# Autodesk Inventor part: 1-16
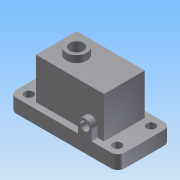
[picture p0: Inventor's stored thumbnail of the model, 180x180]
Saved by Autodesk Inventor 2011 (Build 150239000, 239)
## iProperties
Created: 2014-02
Part Number: 1-16
Document SubType Name: Modeling
Designer: Administrator
Density: 1 g/cm^3
Author: Administrator
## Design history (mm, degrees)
sketch "草图1"
  geometry: L1 (-15.86, 7.751)-(15.86, 7.751); L2 (15.86, 7.751)-(15.86, -7.751); L3 (15.86, -7.751)-(-15.86, -7.751); L4 (-15.86, -7.751)-(-15.86, 7.751); 3 further points
  constraints: 8 end point, 2 midpoint, 2 parallel, 1 horizontal, 1 horizontal alignment, 1 perpendicular, 1 vertical alignment
extrude "拉伸1" new body sketch "草图1" distance "d0" = 4; taper "d1" = 0 deg
sketch "草图2"
  geometry: L1 (-9.931, 5.952)-(9.994, 5.952); L2 (9.994, 5.952)-(9.994, -5.952); L3 (9.994, -5.952)-(-9.931, -5.952); L4 (-9.931, -5.952)-(-9.931, 5.952); 1 further point
  constraints: 8 end point, 2 parallel, 1 horizontal, 1 perpendicular
extrude "拉伸2" join sketch "草图2" distance "d2" = 12; taper "d3" = 0 deg
sketch "草图3"
  geometry: L1 (-9.994, -5.952)-(9.931, -5.952) reference; L2 (-9.994, 5.952)-(-9.994, -5.952) reference; L3 (9.931, 5.952)-(-9.994, 5.952) reference; L4 (9.931, -5.952)-(9.931, 5.952) reference; L5 (-7.989, -4.012)-(7.989, -4.012); L6 (7.989, -4.012)-(7.989, 4.012); L7 (7.989, 4.012)-(-7.989, 4.012); L8 (-7.989, 4.012)-(-7.989, -4.012); 1 further point
  constraints: 8 end point, 2 parallel, 1 horizontal, 1 perpendicular
extrude "拉伸3" cut sketch "草图3" distance "d4" = 14; taper "d5" = 0 deg
fillet "圆角1" dims "d6" = 2
sketch "草图4"
  geometry: C1 r 1.283 at (-12.925, -4.987); A1 r 2 centre (-13.86, 5.751) between (-13.86, 7.751) and (-15.86, 5.751) reference; 2 further points
  constraints: 1 centre point, 3 other
extrude "拉伸4" cut sketch "草图4" distance "d7" = 14; taper "d8" = 0 deg
mirror "镜像1"
sketch "草图5"
  geometry: L1 (-7.989, -4.012)-(-7.989, 4.012) reference; C1 r 3 at (-3.945, 0); 1 further point
  constraints: 1 centre point
  dimensions: "d9" = 6 diameter of C1
extrude "拉伸5" join sketch "草图5" distance "d10" = 2; taper "d11" = 0 deg
sketch "草图6"
  geometry: C1 r 3 at (0, 0) reference; C2 r 2 at (0, 0); 1 further point
  constraints: 1 centre point, 1 coincident
  dimensions: "d12" = 4 diameter of C2
extrude "拉伸6" cut sketch "草图6" stored distance "d13" = 2; taper "d14" = 0 deg
sketch "草图7"
  geometry: L1 (27.72, 4)-(0, 4) reference; L2 (18.059, 6.847)-(18.059, 4); L3 (22.021, 6.847)-(22.021, 4); A1 r 1.981 centre (20.04, 6.847) between (22.021, 6.847) and (18.059, 6.847); 1 further point
  constraints: 4 end point, 2 perpendicular, 2 point on circle, 2 point on line, 2 tangent, 1 centre point
extrude "拉伸7" join sketch "草图7" stored distance "d15" = 2; taper "d16" = 0 deg
sketch "草图8"
  geometry: C1 r 1.3 at (20.04, 6.847); A1 r 1.981 centre (20.04, 6.847) between (22.021, 6.847) and (18.059, 6.847) reference; 1 further point
  constraints: 1 centre point, 1 coincident
  dimensions: "d17" = 2.6 diameter of C1
extrude "拉伸8" cut sketch "草图8" stored distance "d18" = 2; taper "d19" = 0 deg
node "实体1"
